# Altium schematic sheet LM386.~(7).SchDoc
size A4
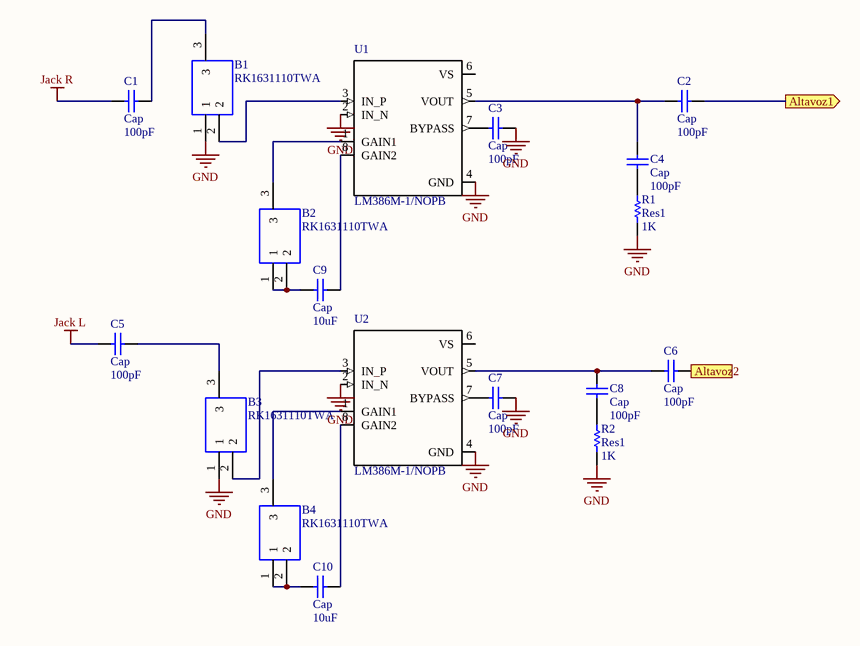
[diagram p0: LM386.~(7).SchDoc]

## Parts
B1  RK1631110TWA  [RK1631110TWA]
B2  RK1631110TWA  [RK1631110TWA]
B3  RK1631110TWA  [RK1631110TWA]
B4  RK1631110TWA  [RK1631110TWA]
C1  Cap  value 100pF  [RAD-0.3]
C2  Cap  value 100pF  [RAD-0.3]
C3  Cap  value 100pF  [RAD-0.3]
C4  Cap  value 100pF  [RAD-0.3]
C5  Cap  value 100pF  [RAD-0.3]
C6  Cap  value 100pF  [RAD-0.3]
C7  Cap  value 100pF  [RAD-0.3]
C8  Cap  value 100pF  [RAD-0.3]
C9  Cap  value 10uF  [RAD-0.3]
C10  Cap  value 10uF  [RAD-0.3]
R1  Res1  value 1K  [AXIAL-0.3]
R2  Res1  value 1K  [AXIAL-0.3]
U1  LM386M-1/NOPB  [SOIC127P600X175-8N]
U2  LM386M-1/NOPB  [SOIC127P600X175-8N]

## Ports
Altavoz1 (out), Altavoz2 (out)

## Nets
GND: B1.1 B3.1 C3.1 C7.2 R1.1 R2.1 U1.2(IN_N) U1.4(GND) U2.2(IN_N) U2.4(GND)
Jack L: C5.2
Jack R: C1.2
Altavoz1: C2.2 ; port Altavoz1
Altavoz2: C6.2 ; port Altavoz2
NetB1_2: B1.2 U1.3(IN_P)
NetB1_3: B1.3 C1.1
NetB2_1: B2.1 B2.2 C9.2
NetB2_3: B2.3 U1.1(GAIN1)
NetB3_2: B3.2 U2.3(IN_P)
NetB3_3: B3.3 C5.1
NetB4_1: B4.1 B4.2 C10.2
NetB4_3: B4.3 U2.1(GAIN1)
NetC2_1: C2.1 C4.2 U1.5(VOUT)
NetC3_2: C3.2 U1.7(BYPASS)
NetC4_1: C4.1 R1.2
NetC6_1: C6.1 C8.2 U2.5(VOUT)
NetC7_1: C7.1 U2.7(BYPASS)
NetC8_1: C8.1 R2.2
NetC9_1: C9.1 U1.8(GAIN2)
NetC10_1: C10.1 U2.8(GAIN2)

Not connected (* = marked no-connect by the designer): U1 6(VS); U2 6(VS)

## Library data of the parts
B1-B4 = RK1631110TWA: Carbon Film Potentiometer RK163 Series with a 6 mm Dia. Shaft 10k 20% 0.1W; Manufacturer_Name: ALPS
C1-C10 = Cap: Capacitor
R1 R2 = Res1: Resistor
U1 U2 = LM386M-1/NOPB: Wide Input Voltage Low Power Audio Amplifier with Internal Gain 8-SOIC 0 to 70; MF: Texas Instruments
